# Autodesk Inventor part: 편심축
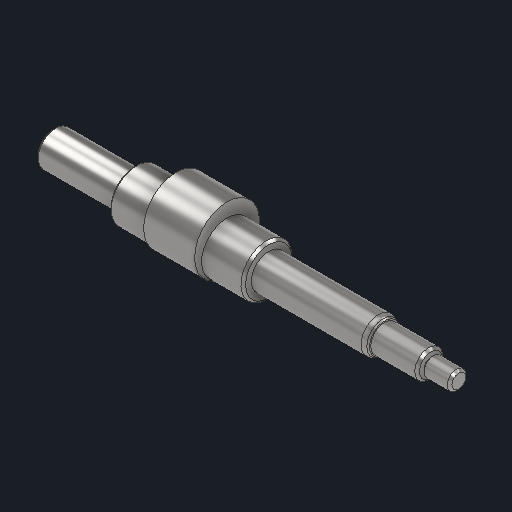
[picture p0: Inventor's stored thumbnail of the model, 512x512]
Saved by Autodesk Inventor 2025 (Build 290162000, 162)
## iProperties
Created: 2025-08
Part Number: 편심축
Material: 강철, 연강
Document SubType Name: Modeling
Designer: infra023
Density: 7.86 g/cm^3
Appearance: 기본값
Author: jhkim
Sending System: Autodesk Inventor 2026
Preprocessor: ST-DEVELOPER v20.1
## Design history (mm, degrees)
feature "솔리드1"
node "솔리드2"
